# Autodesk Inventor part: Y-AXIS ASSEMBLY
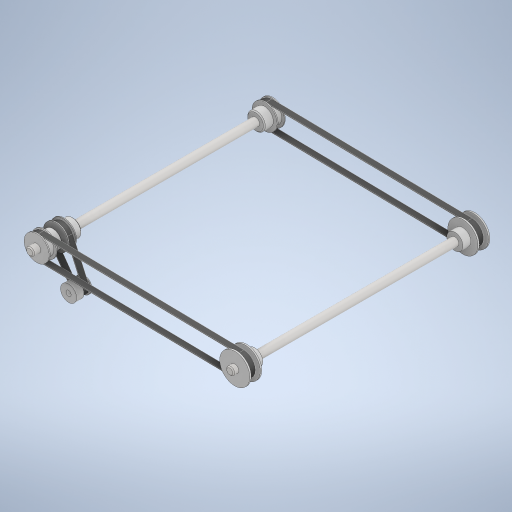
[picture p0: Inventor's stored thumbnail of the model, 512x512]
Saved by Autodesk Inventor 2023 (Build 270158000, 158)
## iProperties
Created: 2025-07
Part Number: Y-AXIS ASSEMBLY
Material: Generic
Document SubType Name: Modeling
Designer: erjon
Density: 1 g/cm^3
Appearance: Default
Author: erjon
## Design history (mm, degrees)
feature "Base1"
feature "Base2"
feature "Base3"
feature "Base4"
feature "Base5"
feature "Base6"
feature "Base7"
feature "Base8"
feature "Base9"
feature "Base10"
feature "Base11"
feature "Base12"
feature "Base13"
feature "Base14"
feature "Base15"
feature "Base16"
feature "Base17"
body "Solid1"
body "Solid2"
body "Solid3"
body "Solid4"
body "Solid5"
body "Solid6"
body "Solid7"
body "Solid8"
body "Solid9"
body "Solid10"
body "Solid11"
body "Solid12"
body "Solid13"
body "Solid14"
body "Solid15"
body "Solid16"
body "Solid17"
